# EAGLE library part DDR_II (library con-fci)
DDR II 240P Source: http://portal.fciconnect.com - gs-12-251.pdf
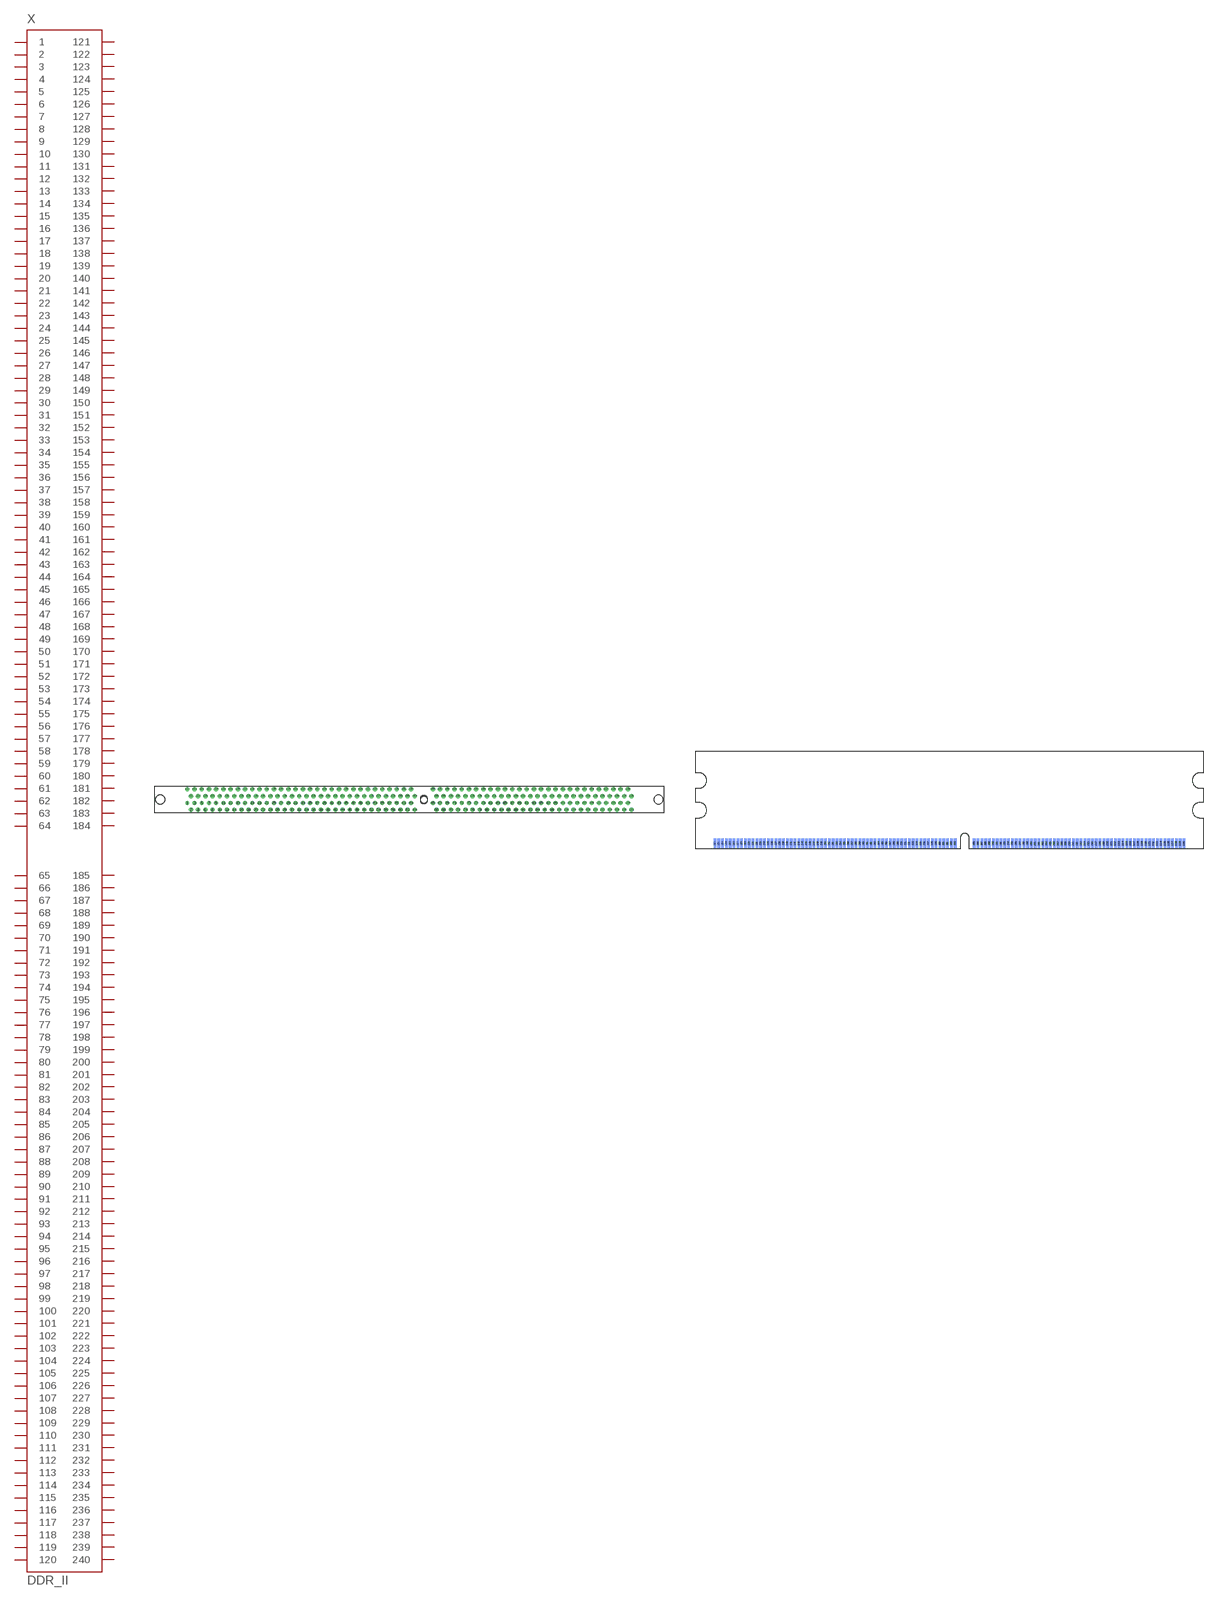
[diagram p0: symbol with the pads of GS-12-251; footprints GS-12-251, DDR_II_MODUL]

Designator prefix X

## DDR_IIGS-12-251 (OC_FARNELL: unknown; OC_NEWARK: unknown)  [GS-12-251]
1  1  pas
2  2  pas
3  3  pas
4  4  pas
5  5  pas
6  6  pas
7  7  pas
8  8  pas
9  9  pas
10  10  pas
11  11  pas
12  12  pas
13  13  pas
14  14  pas
15  15  pas
16  16  pas
17  17  pas
18  18  pas
19  19  pas
20  20  pas
21  21  pas
22  22  pas
23  23  pas
24  24  pas
25  25  pas
26  26  pas
27  27  pas
28  28  pas
29  29  pas
30  30  pas
31  31  pas
32  32  pas
33  33  pas
34  34  pas
35  35  pas
36  36  pas
37  37  pas
38  38  pas
39  39  pas
40  40  pas
41  41  pas
42  42  pas
43  43  pas
44  44  pas
45  45  pas
46  46  pas
47  47  pas
48  48  pas
49  49  pas
50  50  pas
51  51  pas
52  52  pas
53  53  pas
54  54  pas
55  55  pas
56  56  pas
57  57  pas
58  58  pas
59  59  pas
60  60  pas
61  61  pas
62  62  pas
63  63  pas
64  64  pas
65  65  pas
66  66  pas
67  67  pas
68  68  pas
69  69  pas
70  70  pas
71  71  pas
72  72  pas
73  73  pas
74  74  pas
75  75  pas
76  76  pas
77  77  pas
78  78  pas
79  79  pas
80  80  pas
81  81  pas
82  82  pas
83  83  pas
84  84  pas
85  85  pas
86  86  pas
87  87  pas
88  88  pas
89  89  pas
90  90  pas
91  91  pas
92  92  pas
93  93  pas
94  94  pas
95  95  pas
96  96  pas
97  97  pas
98  98  pas
99  99  pas
100  100  pas
101  101  pas
102  102  pas
103  103  pas
104  104  pas
105  105  pas
106  106  pas
107  107  pas
108  108  pas
109  109  pas
110  110  pas
111  111  pas
112  112  pas
113  113  pas
114  114  pas
115  115  pas
116  116  pas
117  117  pas
118  118  pas
119  119  pas
120  120  pas
121  121  pas
122  122  pas
123  123  pas
124  124  pas
125  125  pas
126  126  pas
127  127  pas
128  128  pas
129  129  pas
130  130  pas
131  131  pas
132  132  pas
133  133  pas
134  134  pas
135  135  pas
136  136  pas
137  137  pas
138  138  pas
139  139  pas
140  140  pas
141  141  pas
142  142  pas
143  143  pas
144  144  pas
145  145  pas
146  146  pas
147  147  pas
148  148  pas
149  149  pas
150  150  pas
151  151  pas
152  152  pas
153  153  pas
154  154  pas
155  155  pas
156  156  pas
157  157  pas
158  158  pas
159  159  pas
160  160  pas
161  161  pas
162  162  pas
163  163  pas
164  164  pas
165  165  pas
166  166  pas
167  167  pas
168  168  pas
169  169  pas
170  170  pas
171  171  pas
172  172  pas
173  173  pas
174  174  pas
175  175  pas
176  176  pas
177  177  pas
178  178  pas
179  179  pas
180  180  pas
181  181  pas
182  182  pas
183  183  pas
184  184  pas
185  185  pas
186  186  pas
187  187  pas
188  188  pas
189  189  pas
190  190  pas
191  191  pas
192  192  pas
193  193  pas
194  194  pas
195  195  pas
196  196  pas
197  197  pas
198  198  pas
199  199  pas
200  200  pas
201  201  pas
202  202  pas
203  203  pas
204  204  pas
205  205  pas
206  206  pas
207  207  pas
208  208  pas
209  209  pas
210  210  pas
211  211  pas
212  212  pas
213  213  pas
214  214  pas
215  215  pas
216  216  pas
217  217  pas
218  218  pas
219  219  pas
220  220  pas
221  221  pas
222  222  pas
223  223  pas
224  224  pas
225  225  pas
226  226  pas
227  227  pas
228  228  pas
229  229  pas
230  230  pas
231  231  pas
232  232  pas
233  233  pas
234  234  pas
235  235  pas
236  236  pas
237  237  pas
238  238  pas
239  239  pas
240  240  pas

## DDR_IIDDR_II_MODUL (OC_FARNELL: unknown; OC_NEWARK: unknown)  [DDR_II_MODUL]
Pads as for GS-12-251

## Footprint GS-12-251 (pad centres in mm)
DDR II 240P SOCKETD, 0.039" (1.00mm) PITCH Source: http://portal.fciconnect.com - gs-12-251.pdf
drill 0.7 pad 1.016 round: 1 -65.5,-0.95; 2 -64.5,-2.85; 3 -63.5,-0.95; 4 -62.5,-2.85; 5 -61.5,-0.95; 6 -60.5,-2.85; 7 -59.5,-0.95; 8 -58.5,-2.85; 9 -57.5,-0.95; 10 -56.5,-2.85; 11 -55.5,-0.95; 12 -54.5,-2.85; 13 -53.5,-0.95; 14 -52.5,-2.85; 15 -51.5,-0.95; 16 -50.5,-2.85; 17 -49.5,-0.95; 18 -48.5,-2.85; 19 -47.5,-0.95; 20 -46.5,-2.85; 21 -45.5,-0.95; 22 -44.5,-2.85; 23 -43.5,-0.95; 24 -42.5,-2.85; 25 -41.5,-0.95; 26 -40.5,-2.85; 27 -39.5,-0.95; 28 -38.5,-2.85; 29 -37.5,-0.95; 30 -36.5,-2.85; 31 -35.5,-0.95; 32 -34.5,-2.85; 33 -33.5,-0.95; 34 -32.5,-2.85; 35 -31.5,-0.95; 36 -30.5,-2.85; 37 -29.5,-0.95; 38 -28.5,-2.85; 39 -27.5,-0.95; 40 -26.5,-2.85; 41 -25.5,-0.95; 42 -24.5,-2.85; 43 -23.5,-0.95; 44 -22.5,-2.85; 45 -21.5,-0.95; 46 -20.5,-2.85; 47 -19.5,-0.95; 48 -18.5,-2.85; 49 -17.5,-0.95; 50 -16.5,-2.85; 51 -15.5,-0.95; 52 -14.5,-2.85; 53 -13.5,-0.95; 54 -12.5,-2.85; 55 -11.5,-0.95; 56 -10.5,-2.85; 57 -9.5,-0.95; 58 -8.5,-2.85; 59 -7.5,-0.95; 60 -6.5,-2.85; 61 -5.5,-0.95; 62 -4.5,-2.85; 63 -3.5,-0.95; 64 -2.5,-2.85; 65 2.5,-0.95; 66 3.5,-2.85; 67 4.5,-0.95; 68 5.5,-2.85; 69 6.5,-0.95; 70 7.5,-2.85; 71 8.5,-0.95; 72 9.5,-2.85; 73 10.5,-0.95; 74 11.5,-2.85; 75 12.5,-0.95; 76 13.5,-2.85; 77 14.5,-0.95; 78 15.5,-2.85; 79 16.5,-0.95; 80 17.5,-2.85; 81 18.5,-0.95; 82 19.5,-2.85; 83 20.5,-0.95; 84 21.5,-2.85; 85 22.5,-0.95; 86 23.5,-2.85; 87 24.5,-0.95; 88 25.5,-2.85; 89 26.5,-0.95; 90 27.5,-2.85; 91 28.5,-0.95; 92 29.5,-2.85; 93 30.5,-0.95; 94 31.5,-2.85; 95 32.5,-0.95; 96 33.5,-2.85; 97 34.5,-0.95; 98 35.5,-2.85; 99 36.5,-0.95; 100 37.5,-2.85; 101 38.5,-0.95; 102 39.5,-2.85; 103 40.5,-0.95; 104 41.5,-2.85; 105 42.5,-0.95; 106 43.5,-2.85; 107 44.5,-0.95; 108 45.5,-2.85; 109 46.5,-0.95; 110 47.5,-2.85; 111 48.5,-0.95; 112 49.5,-2.85; 113 50.5,-0.95; 114 51.5,-2.85; 115 52.5,-0.95; 116 53.5,-2.85; 117 54.5,-0.95; 118 55.5,-2.85; 119 56.5,-0.95; 120 57.5,-2.85; 121 -65.5,2.85; 122 -64.5,0.95; 123 -63.5,2.85; 124 -62.5,0.95; 125 -61.5,2.85; 126 -60.5,0.95; 127 -59.5,2.85; 128 -58.5,0.95; 129 -57.5,2.85; 130 -56.5,0.95; 131 -55.5,2.85; 132 -54.5,0.95; 133 -53.5,2.85; 134 -52.5,0.95; 135 -51.5,2.85; 136 -50.5,0.95; 137 -49.5,2.85; 138 -48.5,0.95; 139 -47.5,2.85; 140 -46.5,0.95; 141 -45.5,2.85; 142 -44.5,0.95; 143 -43.5,2.85; 144 -42.5,0.95; 145 -41.5,2.85; 146 -40.5,0.95; 147 -39.5,2.85; 148 -38.5,0.95; 149 -37.5,2.85; 150 -36.5,0.95; 151 -35.5,2.85; 152 -34.5,0.95; 153 -33.5,2.85; 154 -32.5,0.95; 155 -31.5,2.85; 156 -30.5,0.95; 157 -29.5,2.85; 158 -28.5,0.95; 159 -27.5,2.85; 160 -26.5,0.95; 161 -25.5,2.85; 162 -24.5,0.95; 163 -23.5,2.85; 164 -22.5,0.95; 165 -21.5,2.85; 166 -20.5,0.95; 167 -19.5,2.85; 168 -18.5,0.95; 169 -17.5,2.85; 170 -16.5,0.95; 171 -15.5,2.85; 172 -14.5,0.95; 173 -13.5,2.85; 174 -12.5,0.95; 175 -11.5,2.85; 176 -10.5,0.95; 177 -9.5,2.85; 178 -8.5,0.95; 179 -7.5,2.85; 180 -6.5,0.95; 181 -5.5,2.85; 182 -4.5,0.95; 183 -3.5,2.85; 184 -2.5,0.95; 185 2.5,2.85; 186 3.5,0.95; 187 4.5,2.85; 188 5.5,0.95; 189 6.5,2.85; 190 7.5,0.95; 191 8.5,2.85; 192 9.5,0.95; 193 10.5,2.85; 194 11.5,0.95; 195 12.5,2.85; 196 13.5,0.95; 197 14.5,2.85; 198 15.5,0.95; 199 16.5,2.85; 200 17.5,0.95; 201 18.5,2.85; 202 19.5,0.95; 203 20.5,2.85; 204 21.5,0.95; 205 22.5,2.85; 206 23.5,0.95; 207 24.5,2.85; 208 25.5,0.95; 209 26.5,2.85; 210 27.5,0.95; 211 28.5,2.85; 212 29.5,0.95; 213 30.5,2.85; 214 31.5,0.95; 215 32.5,2.85; 216 33.5,0.95; 217 34.5,2.85; 218 35.5,0.95; 219 36.5,2.85; 220 37.5,0.95; 221 38.5,2.85; 222 39.5,0.95; 223 40.5,2.85; 224 41.5,0.95; 225 42.5,2.85; 226 43.5,0.95; 227 44.5,2.85; 228 45.5,0.95; 229 46.5,2.85; 230 47.5,0.95; 231 48.5,2.85; 232 49.5,0.95; 233 50.5,2.85; 234 51.5,0.95; 235 52.5,2.85; 236 53.5,0.95; 237 54.5,2.85; 238 55.5,0.95; 239 56.5,2.85; 240 57.5,0.95
hole 2.45 at 65,0
hole 1.8 at 0,0
hole 2.45 at -73,0

## Footprint DDR_II_MODUL (pad centres in mm)
DDR II 240P MODUL, 0.039" (1.00mm) PITCH Source: http://portal.fciconnect.com - gs-12-251.pdf
smd 0.7 x 2.5: 1 -65.5,1.3; 2 -64.5,1.3; 3 -63.5,1.3; 4 -62.5,1.3; 5 -61.5,1.3; 6 -60.5,1.3; 7 -59.5,1.3; 8 -58.5,1.3; 9 -57.5,1.3; 10 -56.5,1.3; 11 -55.5,1.3; 12 -54.5,1.3; 13 -53.5,1.3; 14 -52.5,1.3; 15 -51.5,1.3; 16 -50.5,1.3; 17 -49.5,1.3; 18 -48.5,1.3; 19 -47.5,1.3; 20 -46.5,1.3; 21 -45.5,1.3; 22 -44.5,1.3; 23 -43.5,1.3; 24 -42.5,1.3; 25 -41.5,1.3; 26 -40.5,1.3; 27 -39.5,1.3; 28 -38.5,1.3; 29 -37.5,1.3; 30 -36.5,1.3; 31 -35.5,1.3; 32 -34.5,1.3; 33 -33.5,1.3; 34 -32.5,1.3; 35 -31.5,1.3; 36 -30.5,1.3; 37 -29.5,1.3; 38 -28.5,1.3; 39 -27.5,1.3; 40 -26.5,1.3; 41 -25.5,1.3; 42 -24.5,1.3; 43 -23.5,1.3; 44 -22.5,1.3; 45 -21.5,1.3; 46 -20.5,1.3; 47 -19.5,1.3; 48 -18.5,1.3; 49 -17.5,1.3; 50 -16.5,1.3; 51 -15.5,1.3; 52 -14.5,1.3; 53 -13.5,1.3; 54 -12.5,1.3; 55 -11.5,1.3; 56 -10.5,1.3; 57 -9.5,1.3; 58 -8.5,1.3; 59 -7.5,1.3; 60 -6.5,1.3; 61 -5.5,1.3; 62 -4.5,1.3; 63 -3.5,1.3; 64 -2.5,1.3; 65 2.5,1.3; 66 3.5,1.3; 67 4.5,1.3; 68 5.5,1.3; 69 6.5,1.3; 70 7.5,1.3; 71 8.5,1.3; 72 9.5,1.3; 73 10.5,1.3; 74 11.5,1.3; 75 12.5,1.3; 76 13.5,1.3; 77 14.5,1.3; 78 15.5,1.3; 79 16.5,1.3; 80 17.5,1.3; 81 18.5,1.3; 82 19.5,1.3; 83 20.5,1.3; 84 21.5,1.3; 85 22.5,1.3; 86 23.5,1.3; 87 24.5,1.3; 88 25.5,1.3; 89 26.5,1.3; 90 27.5,1.3; 91 28.5,1.3; 92 29.5,1.3; 93 30.5,1.3; 94 31.5,1.3; 95 32.5,1.3; 96 33.5,1.3; 97 34.5,1.3; 98 35.5,1.3; 99 36.5,1.3; 100 37.5,1.3; 101 38.5,1.3; 102 39.5,1.3; 103 40.5,1.3; 104 41.5,1.3; 105 42.5,1.3; 106 43.5,1.3; 107 44.5,1.3; 108 45.5,1.3; 109 46.5,1.3; 110 47.5,1.3; 111 48.5,1.3; 112 49.5,1.3; 113 50.5,1.3; 114 51.5,1.3; 115 52.5,1.3; 116 53.5,1.3; 117 54.5,1.3; 118 55.5,1.3; 119 56.5,1.3; 120 57.5,1.3
smd 0.7 x 2.5 bottom: 121 -65.5,1.3; 122 -64.5,1.3; 123 -63.5,1.3; 124 -62.5,1.3; 125 -61.5,1.3; 126 -60.5,1.3; 127 -59.5,1.3; 128 -58.5,1.3; 129 -57.5,1.3; 130 -56.5,1.3; 131 -55.5,1.3; 132 -54.5,1.3; 133 -53.5,1.3; 134 -52.5,1.3; 135 -51.5,1.3; 136 -50.5,1.3; 137 -49.5,1.3; 138 -48.5,1.3; 139 -47.5,1.3; 140 -46.5,1.3; 141 -45.5,1.3; 142 -44.5,1.3; 143 -43.5,1.3; 144 -42.5,1.3; 145 -41.5,1.3; 146 -40.5,1.3; 147 -39.5,1.3; 148 -38.5,1.3; 149 -37.5,1.3; 150 -36.5,1.3; 151 -35.5,1.3; 152 -34.5,1.3; 153 -33.5,1.3; 154 -32.5,1.3; 155 -31.5,1.3; 156 -30.5,1.3; 157 -29.5,1.3; 158 -28.5,1.3; 159 -27.5,1.3; 160 -26.5,1.3; 161 -25.5,1.3; 162 -24.5,1.3; 163 -23.5,1.3; 164 -22.5,1.3; 165 -21.5,1.3; 166 -20.5,1.3; 167 -19.5,1.3; 168 -18.5,1.3; 169 -17.5,1.3; 170 -16.5,1.3; 171 -15.5,1.3; 172 -14.5,1.3; 173 -13.5,1.3; 174 -12.5,1.3; 175 -11.5,1.3; 176 -10.5,1.3; 177 -9.5,1.3; 178 -8.5,1.3; 179 -7.5,1.3; 180 -6.5,1.3; 181 -5.5,1.3; 182 -4.5,1.3; 183 -3.5,1.3; 184 -2.5,1.3; 185 2.5,1.3; 186 3.5,1.3; 187 4.5,1.3; 188 5.5,1.3; 189 6.5,1.3; 190 7.5,1.3; 191 8.5,1.3; 192 9.5,1.3; 193 10.5,1.3; 194 11.5,1.3; 195 12.5,1.3; 196 13.5,1.3; 197 14.5,1.3; 198 15.5,1.3; 199 16.5,1.3; 200 17.5,1.3; 201 18.5,1.3; 202 19.5,1.3; 203 20.5,1.3; 204 21.5,1.3; 205 22.5,1.3; 206 23.5,1.3; 207 24.5,1.3; 208 25.5,1.3; 209 26.5,1.3; 210 27.5,1.3; 211 28.5,1.3; 212 29.5,1.3; 213 30.5,1.3; 214 31.5,1.3; 215 32.5,1.3; 216 33.5,1.3; 217 34.5,1.3; 218 35.5,1.3; 219 36.5,1.3; 220 37.5,1.3; 221 38.5,1.3; 222 39.5,1.3; 223 40.5,1.3; 224 41.5,1.3; 225 42.5,1.3; 226 43.5,1.3; 227 44.5,1.3; 228 45.5,1.3; 229 46.5,1.3; 230 47.5,1.3; 231 48.5,1.3; 232 49.5,1.3; 233 50.5,1.3; 234 51.5,1.3; 235 52.5,1.3; 236 53.5,1.3; 237 54.5,1.3; 238 55.5,1.3; 239 56.5,1.3; 240 57.5,1.3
